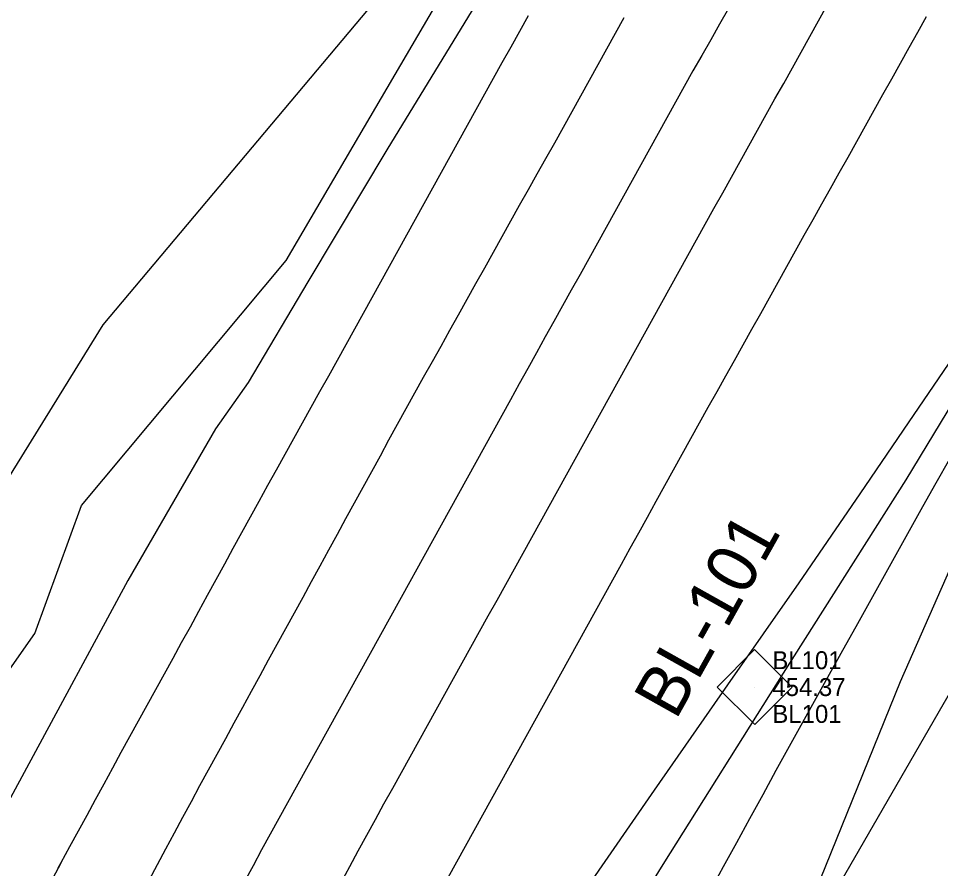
# Model space of a CAD drawing. Extents: x 2074109 to 2077820, y 741079 to 746031.
# Drawn here: x 2074752.4 to 2074881.1, y 742141.5 to 742260.2 of the extents above; entities that cross this region are included whole.
import ezdxf

# ---------------------------------------------------------------- set-up
doc = ezdxf.new("R2010")
doc.units = 0
for name, color, linetype in [('CTL Secondary Horizontal and Vertical CELL', 7, 'Continuous'), ('CTL Secondary Horizontal and Vertical Cogo Comment', 7, 'Continuous'), ('CTL Secondary Horizontal and Vertical Cogo Elevation', 7, 'Continuous'), ('CTL Secondary Horizontal and Vertical Cogo Number', 7, 'Continuous'), ('Exist Guardrail Cable Guide Rail', 7, 'Continuous'), ('Exist Horizontal Alignment', 7, 'Continuous'), ('Exist Horizontal Baseline Alignment Station Label', 7, 'Continuous'), ('Exist Roads EOP', 7, 'Continuous'), ('Exist Roads EOT', 7, 'Continuous'), ('Exist Structure Minor Pipes RCP 24 Inch', 7, 'Continuous'), ('Exist Utilities Telephone UG FO SUE LOS B', 7, 'Continuous'), ('Exist Vegetation Woods Line', 7, 'Continuous')]:
    doc.layers.add(name, color=color, linetype=linetype)

msp = doc.modelspace()

# ---------------------------------------------------------------- linework, layer by layer
at = {"layer": 'CTL Secondary Horizontal and Vertical CELL'}
msp.add_line((2074855.15, 742166.85), (2074855.15, 742166.85), dxfattribs=at)
msp.add_lwpolyline([(2074849.94, 742166.86), (2074855.18, 742172.11), (2074860.43, 742166.85), (2074855.19, 742161.61)], close=True, dxfattribs=at)
at = {"layer": 'Exist Guardrail Cable Guide Rail'}
msp.add_lwpolyline([(2074899.36, 742232.91), (2074888.78, 742216.41), (2074876.27, 742195.78), (2074859.16, 742168.78), (2074842.38, 742142.08), (2074825.57, 742114.96), (2074808.9, 742087.84), (2074792.03, 742058.51), (2074770.99, 742020.02), (2074765.4, 742008.78)], dxfattribs=at)
at = {"layer": 'Exist Horizontal Alignment'}
msp.add_arc((2079979.02, 739333.44), 5846.83, 150.58124, 152.982068, dxfattribs=at)
at = {"layer": 'Exist Roads EOP'}
for points in [[(2074946.03, 742491.1), (2074936.44, 742472.71), (2074925.7, 742453.35), (2074913.24, 742431.17), (2074898.61, 742404.49), (2074883.66, 742377.59), (2074866.99, 742347.78), (2074852.89, 742322.35), (2074840.31, 742299.07), (2074831.68, 742283.69), (2074824.98, 742273.09), (2074821.75, 742269.21), (2074819.4, 742266.98), (2074817.67, 742264.47), (2074804.01, 742242.07), (2074792.81, 742223.43), (2074784.5, 742209.34), (2074779.94, 742202.91), (2074767.71, 742181.73), (2074753.23, 742154.94), (2074740.59, 742131.58)], [(2075045.28, 742485.48), (2075032.39, 742461.82), (2075017.41, 742432.2), (2075008.62, 742415.56), (2074994.4, 742390.44), (2074976.29, 742358.27), (2074960.6, 742330.46), (2074947.27, 742306.52), (2074935.38, 742284.89), (2074921.31, 742258.95), (2074908.74, 742236.47), (2074898.47, 742217.63), (2074887.04, 742193.79), (2074875.51, 742167.59), (2074863.59, 742138.18), (2074850.64, 742104.73), (2074841.42, 742081.23), (2074837.2, 742071.06), (2074833.01, 742062.28), (2074824.64, 742046.55), (2074815.15, 742028.51), (2074804.68, 742008.24), (2074793.6, 741986.73), (2074789.72, 741978.96)], [(2074831.71, 742138.74), (2074841.22, 742152.47), (2074851.46, 742167.15), (2074861.38, 742181.39), (2074869.93, 742193.81), (2074877.46, 742204.87), (2074884.35, 742215.01), (2074890.63, 742224.3), (2074896.3, 742232.82), (2074901.79, 742241.22), (2074907.49, 742250.18), (2074913.75, 742260.62)]]:
    msp.add_lwpolyline(points, dxfattribs=at)
at = {"layer": 'Exist Roads EOT'}
for points in [[(2074797.48, 742139.59), (2074798.67, 742141.79), (2074799.87, 742143.98), (2074801.06, 742146.18), (2074802.25, 742148.38), (2074803.45, 742150.57), (2074804.67, 742152.75), (2074805.88, 742154.94), (2074807.09, 742157.12), (2074808.31, 742159.31), (2074809.52, 742161.5), (2074810.73, 742163.68), (2074811.95, 742165.87), (2074813.16, 742168.05), (2074814.37, 742170.24), (2074815.59, 742172.42), (2074816.8, 742174.61), (2074818.01, 742176.79), (2074819.24, 742178.97), (2074820.46, 742181.16), (2074821.68, 742183.34), (2074822.9, 742185.52), (2074824.1, 742187.71), (2074825.31, 742189.9), (2074826.52, 742192.09), (2074827.73, 742194.27), (2074828.94, 742196.46), (2074830.15, 742198.65), (2074831.35, 742200.84), (2074832.56, 742203.03), (2074833.77, 742205.22), (2074834.98, 742207.4), (2074836.19, 742209.59), (2074837.4, 742211.78), (2074838.6, 742213.97), (2074839.81, 742216.16), (2074841.01, 742218.35), (2074842.23, 742220.53), (2074843.44, 742222.72), (2074844.65, 742224.9), (2074845.87, 742227.09), (2074847.08, 742229.27), (2074848.3, 742231.46), (2074849.51, 742233.64), (2074850.73, 742235.83), (2074851.94, 742238.01), (2074853.16, 742240.2), (2074854.37, 742242.38), (2074855.58, 742244.57), (2074856.8, 742246.75), (2074858.02, 742248.93), (2074859.24, 742251.11), (2074860.47, 742253.29), (2074861.68, 742255.48), (2074862.89, 742257.67), (2074864.1, 742259.85), (2074865.31, 742262.04)], [(2074823.56, 742260.53), (2074822.35, 742258.34), (2074821.14, 742256.16), (2074819.92, 742253.97), (2074818.71, 742251.78), (2074817.5, 742249.6), (2074816.29, 742247.41), (2074815.08, 742245.23), (2074813.87, 742243.04), (2074812.66, 742240.85), (2074811.45, 742238.67), (2074810.24, 742236.48), (2074809.03, 742234.29), (2074807.81, 742232.11), (2074806.6, 742229.92), (2074805.39, 742227.73), (2074804.18, 742225.55), (2074802.96, 742223.36), (2074801.75, 742221.18), (2074800.54, 742218.99), (2074799.32, 742216.81), (2074798.11, 742214.62), (2074796.9, 742212.44), (2074795.69, 742210.25), (2074794.47, 742208.07), (2074793.26, 742205.88), (2074792.04, 742203.7), (2074790.83, 742201.51), (2074789.62, 742199.33), (2074788.4, 742197.14), (2074787.19, 742194.96), (2074785.98, 742192.77), (2074784.77, 742190.58), (2074783.57, 742188.39), (2074782.37, 742186.19), (2074781.18, 742184), (2074779.98, 742181.81), (2074778.78, 742179.62), (2074777.58, 742177.42), (2074776.38, 742175.23), (2074775.17, 742173.04), (2074773.97, 742170.85), (2074772.76, 742168.66), (2074771.56, 742166.47), (2074770.35, 742164.28), (2074769.15, 742162.09), (2074767.94, 742159.9), (2074766.75, 742157.71), (2074765.55, 742155.51), (2074764.35, 742153.32), (2074763.16, 742151.12), (2074761.96, 742148.93), (2074760.76, 742146.73), (2074759.57, 742144.54), (2074758.37, 742142.34), (2074757.95, 742141.56)], [(2074851.52, 742261.54), (2074850.3, 742259.36), (2074849.05, 742257.19), (2074847.81, 742255.02), (2074846.57, 742252.85), (2074845.34, 742250.67), (2074844.13, 742248.49), (2074842.92, 742246.3), (2074841.71, 742244.11), (2074840.5, 742241.93), (2074839.29, 742239.74), (2074838.08, 742237.55), (2074836.87, 742235.37), (2074835.66, 742233.18), (2074834.45, 742230.99), (2074833.23, 742228.81), (2074832.02, 742226.62), (2074830.81, 742224.43), (2074829.59, 742222.25), (2074828.37, 742220.07), (2074827.15, 742217.89), (2074825.93, 742215.71), (2074824.72, 742213.52), (2074823.51, 742211.33), (2074822.3, 742209.15), (2074821.09, 742206.96), (2074819.88, 742204.77), (2074818.67, 742202.58), (2074817.46, 742200.4), (2074816.25, 742198.21), (2074815.04, 742196.02), (2074813.83, 742193.83), (2074812.62, 742191.65), (2074811.41, 742189.46), (2074810.21, 742187.27), (2074809, 742185.08), (2074807.8, 742182.89), (2074807.29, 742181.96)], [(2074770.66, 742139.88), (2074771.84, 742142.08), (2074773.03, 742144.28), (2074774.21, 742146.49), (2074775.4, 742148.69), (2074776.58, 742150.89), (2074777.77, 742153.09), (2074778.97, 742155.28), (2074780.16, 742157.48), (2074781.36, 742159.67), (2074782.55, 742161.87), (2074783.75, 742164.06), (2074784.95, 742166.26), (2074786.15, 742168.45), (2074787.35, 742170.64), (2074788.55, 742172.83), (2074789.75, 742175.02), (2074790.95, 742177.22), (2074792.16, 742179.41), (2074793.35, 742181.6), (2074794.55, 742183.79), (2074795.75, 742185.99), (2074796.95, 742188.18), (2074798.15, 742190.37), (2074799.35, 742192.57), (2074800.55, 742194.76), (2074801.75, 742196.95), (2074802.95, 742199.14), (2074804.15, 742201.34), (2074805.36, 742203.53), (2074806.56, 742205.72), (2074807.78, 742207.9), (2074808.99, 742210.09), (2074810.21, 742212.27), (2074811.43, 742214.45), (2074812.64, 742216.64), (2074813.86, 742218.82), (2074815.08, 742221), (2074816.29, 742223.19), (2074817.51, 742225.37), (2074818.73, 742227.55), (2074819.94, 742229.74), (2074821.16, 742231.92), (2074822.38, 742234.1), (2074823.61, 742236.28), (2074824.83, 742238.46), (2074826.06, 742240.64), (2074827.28, 742242.82), (2074828.5, 742245), (2074829.71, 742247.19), (2074830.91, 742249.38), (2074832.12, 742251.56), (2074833.33, 742253.75), (2074834.54, 742255.94), (2074835.76, 742258.12), (2074836.98, 742260.3)], [(2074879.14, 742260.41), (2074877.92, 742258.23), (2074876.7, 742256.05), (2074875.48, 742253.86), (2074874.26, 742251.68), (2074873.05, 742249.5), (2074871.83, 742247.32), (2074870.61, 742245.14), (2074869.39, 742242.96), (2074868.17, 742240.77), (2074866.95, 742238.59), (2074865.73, 742236.41), (2074864.51, 742234.23), (2074863.29, 742232.04), (2074862.07, 742229.86), (2074860.85, 742227.68), (2074859.63, 742225.5), (2074858.42, 742223.31), (2074857.2, 742221.13), (2074855.98, 742218.95), (2074854.76, 742216.77), (2074853.54, 742214.58), (2074852.32, 742212.4), (2074851.11, 742210.22), (2074849.89, 742208.04), (2074848.67, 742205.85), (2074847.46, 742203.67), (2074846.25, 742201.48), (2074845.04, 742199.29), (2074843.83, 742197.1), (2074842.62, 742194.92), (2074841.41, 742192.73), (2074840.2, 742190.54), (2074838.99, 742188.35), (2074837.78, 742186.17), (2074836.57, 742183.98), (2074835.36, 742181.79), (2074834.15, 742179.6), (2074832.94, 742177.42), (2074831.73, 742175.23), (2074830.52, 742173.04), (2074829.31, 742170.85), (2074828.1, 742168.67), (2074826.89, 742166.48), (2074825.68, 742164.29), (2074824.46, 742162.11), (2074823.25, 742159.92), (2074822.04, 742157.73), (2074820.83, 742155.54), (2074819.62, 742153.36), (2074818.42, 742151.17), (2074817.21, 742148.98), (2074816, 742146.79), (2074814.79, 742144.6), (2074813.59, 742142.41), (2074812.38, 742140.22)], [(2074807.29, 742181.96), (2074791.21, 742152.87), (2074790, 742150.68), (2074788.78, 742148.5), (2074787.57, 742146.31), (2074786.37, 742144.12), (2074785.18, 742141.92), (2074783.99, 742139.72)], [(2074758.35, 742142.29), (2074749.53, 742125.74)]]:
    msp.add_lwpolyline(points, dxfattribs=at)
at = {"layer": 'Exist Structure Minor Pipes RCP 24 Inch'}
msp.add_line((2074709.57, 741866.73), (2074933.64, 742254.78), dxfattribs=at)
at = {"layer": 'Exist Utilities Telephone UG FO SUE LOS B'}
msp.add_lwpolyline([(2074677.89, 742048.45), (2074687.56, 742064.31), (2074720.62, 742125.71), (2074754.72, 742174.31), (2074761.25, 742192.2), (2074789.79, 742226.39), (2074932.06, 742469.18), (2074970.24, 742541.68)], dxfattribs=at)
at = {"layer": 'Exist Vegetation Woods Line'}
msp.add_lwpolyline([(2074747.07, 742324.96), (2074761.88, 742322.25), (2074776.72, 742326.66), (2074781.96, 742326.06), (2074790.35, 742317.46), (2074795.87, 742306.54), (2074804.96, 742303.82), (2074811.11, 742311.39), (2074814.94, 742316.1), (2074820.92, 742316.08), (2074827.48, 742312.14), (2074826.11, 742302.39), (2074801.26, 742261.45), (2074764.21, 742217.4), (2074746.74, 742189.19)], dxfattribs=at)

# ---------------------------------------------------------------- texts
at = {"layer": 'CTL Secondary Horizontal and Vertical Cogo Comment'}
msp.add_text('BL101', height=2.5, dxfattribs=at).set_placement((2074857.65, 742161.85))
at = {"layer": 'CTL Secondary Horizontal and Vertical Cogo Elevation'}
msp.add_text('454.37', height=2.5, dxfattribs=at).set_placement((2074857.65, 742165.6))
at = {"layer": 'CTL Secondary Horizontal and Vertical Cogo Number'}
msp.add_text('BL101', height=2.5, dxfattribs=at).set_placement((2074857.65, 742169.35))
at = {"layer": 'Exist Horizontal Baseline Alignment Station Label'}
msp.add_text('BL-101', height=7, rotation=60.742, dxfattribs=at).set_placement((2074844.17, 742162.11))

doc.saveas('drawing.dxf')
